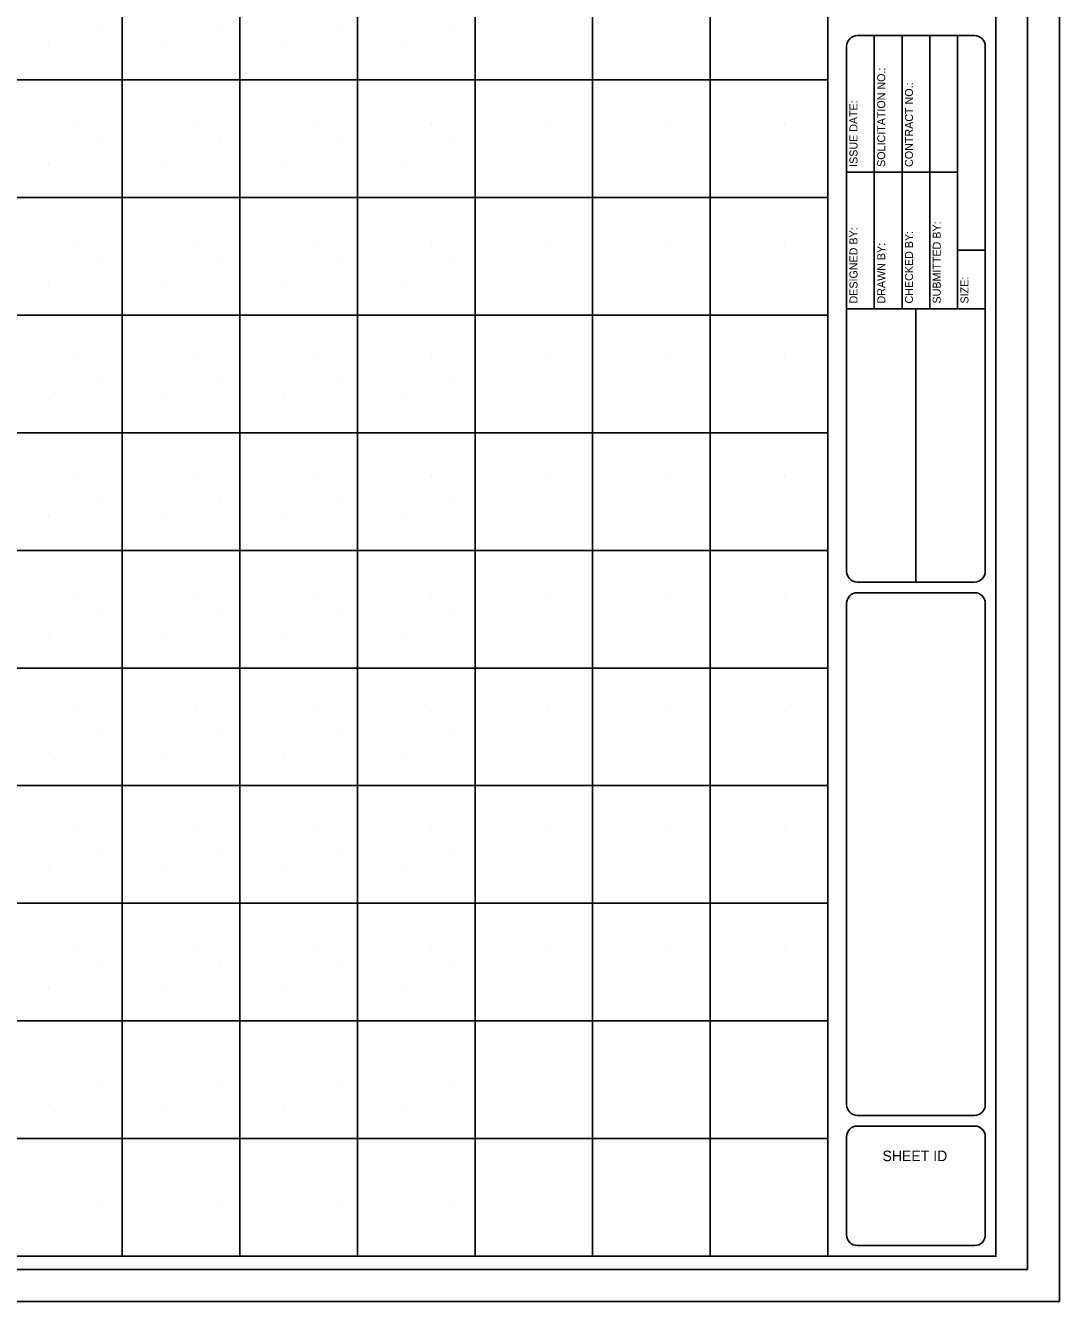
# Model space of a CAD drawing. Extents: x -0.05 to 1.19, y 0 to 0.86.
# Drawn here: x 0.8813 to 1.189, y 0 to 0.3796 of the extents above; entities that cross this region are included whole.
import ezdxf

# ---------------------------------------------------------------- set-up
doc = ezdxf.new("R2010")
doc.units = 0
for name, color, linetype in [('G-ANNO-NPLT', 7, 'Continuous'), ('G-ANNO-TEXT', 7, 'Continuous'), ('G-ANNO-TTLB', 7, 'Continuous'), ('G-ANNO-TTLB-GRID', 7, 'Continuous')]:
    doc.layers.add(name, color=color, linetype=linetype)

msp = doc.modelspace()

# ---------------------------------------------------------------- linework, layer by layer
at = {"layer": 'G-ANNO-NPLT'}
for p, q in [((0.904075, 0.3794687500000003), (0.904075, 0.3794687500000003)), ((0.939075, 0.3794687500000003), (0.939075, 0.3794687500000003)), ((0.9740749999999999, 0.3794687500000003), (0.9740749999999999, 0.3794687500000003)), ((1.009075, 0.3794687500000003), (1.009075, 0.3794687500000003)), ((0.888075, 0.3734687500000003), (0.888075, 0.3734687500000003)), ((0.923075, 0.3734687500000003), (0.923075, 0.3734687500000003)), ((0.958075, 0.3734687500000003), (0.958075, 0.3734687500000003)), ((0.9930749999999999, 0.3734687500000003), (0.9930749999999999, 0.3734687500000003)), ((0.897075, 0.35046874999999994), (0.897075, 0.35046874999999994)), ((0.932075, 0.35046874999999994), (0.932075, 0.35046874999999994)), ((0.9670749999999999, 0.35046874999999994), (0.9670749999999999, 0.35046874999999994)), ((1.002075, 0.35046874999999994), (1.002075, 0.35046874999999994)), ((1.037075, 0.35046874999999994), (1.037075, 0.35046874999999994)), ((1.072075, 0.35046874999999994), (1.072075, 0.35046874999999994)), ((1.107075, 0.35046874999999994), (1.107075, 0.35046874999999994)), ((0.904075, 0.34446875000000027), (0.904075, 0.34446875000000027)), ((0.939075, 0.34446875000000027), (0.939075, 0.34446875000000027)), ((0.9740749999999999, 0.34446875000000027), (0.9740749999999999, 0.34446875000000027)), ((1.009075, 0.34446875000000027), (1.009075, 0.34446875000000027)), ((0.888075, 0.33846875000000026), (0.888075, 0.33846875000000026)), ((0.923075, 0.33846875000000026), (0.923075, 0.33846875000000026)), ((0.958075, 0.33846875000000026), (0.958075, 0.33846875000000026)), ((0.9930749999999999, 0.33846875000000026), (0.9930749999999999, 0.33846875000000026)), ((0.897075, 0.3154687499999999), (0.897075, 0.3154687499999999)), ((0.932075, 0.3154687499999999), (0.932075, 0.3154687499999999)), ((0.9670749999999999, 0.3154687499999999), (0.9670749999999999, 0.3154687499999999)), ((1.002075, 0.3154687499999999), (1.002075, 0.3154687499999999)), ((1.037075, 0.3154687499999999), (1.037075, 0.3154687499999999)), ((1.072075, 0.3154687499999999), (1.072075, 0.3154687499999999)), ((1.107075, 0.3154687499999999), (1.107075, 0.3154687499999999)), ((0.904075, 0.3094687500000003), (0.904075, 0.3094687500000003)), ((0.939075, 0.3094687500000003), (0.939075, 0.3094687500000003)), ((0.9740749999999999, 0.3094687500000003), (0.9740749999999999, 0.3094687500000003)), ((1.009075, 0.3094687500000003), (1.009075, 0.3094687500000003)), ((0.888075, 0.3034687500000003), (0.888075, 0.3034687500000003)), ((0.923075, 0.3034687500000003), (0.923075, 0.3034687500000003)), ((0.958075, 0.3034687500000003), (0.958075, 0.3034687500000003)), ((0.9930749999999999, 0.3034687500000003), (0.9930749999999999, 0.3034687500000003)), ((0.897075, 0.28046874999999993), (0.897075, 0.28046874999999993)), ((0.932075, 0.28046874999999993), (0.932075, 0.28046874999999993)), ((0.9670749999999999, 0.28046874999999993), (0.9670749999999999, 0.28046874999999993)), ((1.002075, 0.28046874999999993), (1.002075, 0.28046874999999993)), ((1.037075, 0.28046874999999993), (1.037075, 0.28046874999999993)), ((1.072075, 0.28046874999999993), (1.072075, 0.28046874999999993)), ((1.107075, 0.28046874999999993), (1.107075, 0.28046874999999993)), ((0.904075, 0.27446875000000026), (0.904075, 0.27446875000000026)), ((0.939075, 0.27446875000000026), (0.939075, 0.27446875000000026)), ((0.9740749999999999, 0.27446875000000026), (0.9740749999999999, 0.27446875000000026)), ((1.009075, 0.27446875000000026), (1.009075, 0.27446875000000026)), ((0.888075, 0.26846875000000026), (0.888075, 0.26846875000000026)), ((0.923075, 0.26846875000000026), (0.923075, 0.26846875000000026)), ((0.958075, 0.26846875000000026), (0.958075, 0.26846875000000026)), ((0.9930749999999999, 0.26846875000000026), (0.9930749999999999, 0.26846875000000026)), ((0.897075, 0.24546874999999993), (0.897075, 0.24546874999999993)), ((0.932075, 0.24546874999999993), (0.932075, 0.24546874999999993)), ((0.9670749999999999, 0.24546874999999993), (0.9670749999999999, 0.24546874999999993)), ((1.002075, 0.24546874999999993), (1.002075, 0.24546874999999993)), ((1.037075, 0.24546874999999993), (1.037075, 0.24546874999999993)), ((1.072075, 0.24546874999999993), (1.072075, 0.24546874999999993)), ((1.107075, 0.24546874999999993), (1.107075, 0.24546874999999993)), ((0.904075, 0.23946875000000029), (0.904075, 0.23946875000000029)), ((0.939075, 0.23946875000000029), (0.939075, 0.23946875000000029)), ((0.9740749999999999, 0.23946875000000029), (0.9740749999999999, 0.23946875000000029)), ((1.009075, 0.23946875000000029), (1.009075, 0.23946875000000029)), ((0.888075, 0.23346875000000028), (0.888075, 0.23346875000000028)), ((0.923075, 0.23346875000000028), (0.923075, 0.23346875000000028)), ((0.958075, 0.23346875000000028), (0.958075, 0.23346875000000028)), ((0.9930749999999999, 0.23346875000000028), (0.9930749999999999, 0.23346875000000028)), ((0.897075, 0.21046874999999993), (0.897075, 0.21046874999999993)), ((0.932075, 0.21046874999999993), (0.932075, 0.21046874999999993)), ((0.9670749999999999, 0.21046874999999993), (0.9670749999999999, 0.21046874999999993)), ((1.002075, 0.21046874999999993), (1.002075, 0.21046874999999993)), ((1.037075, 0.21046874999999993), (1.037075, 0.21046874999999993)), ((1.072075, 0.21046874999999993), (1.072075, 0.21046874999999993)), ((1.107075, 0.21046874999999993), (1.107075, 0.21046874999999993)), ((0.904075, 0.20446875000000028), (0.904075, 0.20446875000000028)), ((0.939075, 0.20446875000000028), (0.939075, 0.20446875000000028)), ((0.9740749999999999, 0.20446875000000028), (0.9740749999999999, 0.20446875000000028)), ((1.009075, 0.20446875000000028), (1.009075, 0.20446875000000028)), ((0.888075, 0.19846875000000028), (0.888075, 0.19846875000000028)), ((0.923075, 0.19846875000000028), (0.923075, 0.19846875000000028)), ((0.958075, 0.19846875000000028), (0.958075, 0.19846875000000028)), ((0.9930749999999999, 0.19846875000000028), (0.9930749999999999, 0.19846875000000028)), ((0.897075, 0.17546874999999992), (0.897075, 0.17546874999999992)), ((0.932075, 0.17546874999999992), (0.932075, 0.17546874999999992)), ((0.9670749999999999, 0.17546874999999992), (0.9670749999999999, 0.17546874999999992)), ((1.002075, 0.17546874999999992), (1.002075, 0.17546874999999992)), ((1.037075, 0.17546874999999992), (1.037075, 0.17546874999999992)), ((1.072075, 0.17546874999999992), (1.072075, 0.17546874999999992)), ((1.107075, 0.17546874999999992), (1.107075, 0.17546874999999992)), ((0.904075, 0.16946875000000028), (0.904075, 0.16946875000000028)), ((0.939075, 0.16946875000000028), (0.939075, 0.16946875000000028)), ((0.9740749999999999, 0.16946875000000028), (0.9740749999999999, 0.16946875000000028)), ((1.009075, 0.16946875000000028), (1.009075, 0.16946875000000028)), ((0.888075, 0.16346875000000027), (0.888075, 0.16346875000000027)), ((0.923075, 0.16346875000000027), (0.923075, 0.16346875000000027)), ((0.958075, 0.16346875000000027), (0.958075, 0.16346875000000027)), ((0.9930749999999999, 0.16346875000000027), (0.9930749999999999, 0.16346875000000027)), ((0.897075, 0.14046874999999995), (0.897075, 0.14046874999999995)), ((0.932075, 0.14046874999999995), (0.932075, 0.14046874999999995)), ((0.9670749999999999, 0.14046874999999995), (0.9670749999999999, 0.14046874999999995)), ((1.002075, 0.14046874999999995), (1.002075, 0.14046874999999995)), ((1.037075, 0.14046874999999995), (1.037075, 0.14046874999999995)), ((1.072075, 0.14046874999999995), (1.072075, 0.14046874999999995)), ((1.107075, 0.14046874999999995), (1.107075, 0.14046874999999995)), ((0.904075, 0.13446875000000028), (0.904075, 0.13446875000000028)), ((0.939075, 0.13446875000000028), (0.939075, 0.13446875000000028)), ((0.9740749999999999, 0.13446875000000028), (0.9740749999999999, 0.13446875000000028)), ((1.009075, 0.13446875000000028), (1.009075, 0.13446875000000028)), ((0.888075, 0.1284687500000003), (0.888075, 0.1284687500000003)), ((0.923075, 0.1284687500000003), (0.923075, 0.1284687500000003)), ((0.958075, 0.1284687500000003), (0.958075, 0.1284687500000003)), ((0.9930749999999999, 0.1284687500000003), (0.9930749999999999, 0.1284687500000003)), ((0.897075, 0.10546874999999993), (0.897075, 0.10546874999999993)), ((0.932075, 0.10546874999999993), (0.932075, 0.10546874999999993)), ((0.9670749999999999, 0.10546874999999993), (0.9670749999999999, 0.10546874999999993)), ((1.002075, 0.10546874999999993), (1.002075, 0.10546874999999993)), ((1.037075, 0.10546874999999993), (1.037075, 0.10546874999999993)), ((1.072075, 0.10546874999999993), (1.072075, 0.10546874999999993)), ((1.107075, 0.10546874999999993), (1.107075, 0.10546874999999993)), ((0.904075, 0.09946875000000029), (0.904075, 0.09946875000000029)), ((0.939075, 0.09946875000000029), (0.939075, 0.09946875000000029)), ((0.9740749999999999, 0.09946875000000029), (0.9740749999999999, 0.09946875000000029)), ((1.009075, 0.09946875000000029), (1.009075, 0.09946875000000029)), ((0.888075, 0.09346875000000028), (0.888075, 0.09346875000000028)), ((0.923075, 0.09346875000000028), (0.923075, 0.09346875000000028)), ((0.958075, 0.09346875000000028), (0.958075, 0.09346875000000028)), ((0.9930749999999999, 0.09346875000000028), (0.9930749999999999, 0.09346875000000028)), ((0.904075, 0.06446875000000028), (0.904075, 0.06446875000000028)), ((0.939075, 0.06446875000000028), (0.939075, 0.06446875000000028)), ((0.9740749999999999, 0.06446875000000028), (0.9740749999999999, 0.06446875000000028)), ((1.009075, 0.06446875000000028), (1.009075, 0.06446875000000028)), ((0.888075, 0.05846875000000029), (0.888075, 0.05846875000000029)), ((0.923075, 0.05846875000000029), (0.923075, 0.05846875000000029)), ((0.958075, 0.05846875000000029), (0.958075, 0.05846875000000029)), ((0.9930749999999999, 0.05846875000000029), (0.9930749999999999, 0.05846875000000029)), ((0.904075, 0.02946875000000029), (0.904075, 0.02946875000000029)), ((0.939075, 0.02946875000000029), (0.939075, 0.02946875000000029)), ((0.9740749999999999, 0.02946875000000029), (0.9740749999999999, 0.02946875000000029)), ((1.009075, 0.02946875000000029), (1.009075, 0.02946875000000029))]:
    msp.add_line(p, q, dxfattribs=at)
msp.add_lwpolyline([(0.009524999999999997, 0.8314749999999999), (1.179475, 0.8314749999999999), (1.179475, 0.009525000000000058), (0.009524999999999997, 0.009524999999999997)], close=True, dxfattribs=at)
at = {"layer": 'G-ANNO-TTLB'}
for p, q in [((1.1338947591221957, 0.2953398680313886), (1.1338947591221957, 0.37661986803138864)), ((1.1421497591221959, 0.2953398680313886), (1.1421497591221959, 0.37661986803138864)), ((1.1504047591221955, 0.2953398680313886), (1.1504047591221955, 0.37661986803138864)), ((1.1586597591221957, 0.2953398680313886), (1.1586597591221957, 0.37661986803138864)), ((1.1586597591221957, 0.3359798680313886), (1.1256450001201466, 0.3359798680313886)), ((1.1669199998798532, 0.3127552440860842), (1.1586597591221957, 0.3127552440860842)), ((1.1256450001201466, 0.2953398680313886), (1.1669199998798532, 0.2953398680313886)), ((1.1462772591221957, 0.21405986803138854), (1.1462772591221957, 0.2953398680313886)), ((1.1462772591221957, 0.21405986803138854), (1.1462772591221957, 0.2953398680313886))]:
    msp.add_line(p, q, dxfattribs=at)
for points in [[(0, 0.841), (1.189, 0.841), (1.189, 0), (0, 0)], [(0.035074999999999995, 0.81846875), (1.1700949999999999, 0.81846875), (1.1700949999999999, 0.013468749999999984), (0.035074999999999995, 0.01346874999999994)], [(1.120075, 0.57346875), (1.1700949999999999, 0.57346875), (1.1700949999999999, 0.013468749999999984), (1.120075, 0.01346874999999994)]]:
    msp.add_lwpolyline(points, close=True, dxfattribs=at)
for points in [[(1.1637449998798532, 0.3766198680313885), (1.1288200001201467, 0.3766198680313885)], [(1.1256450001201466, 0.37344486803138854), (1.1256450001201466, 0.21723486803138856)], [(1.1669199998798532, 0.21723486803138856), (1.1669199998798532, 0.37344486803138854)], [(1.1288200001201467, 0.21405986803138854), (1.1637449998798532, 0.21405986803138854)], [(1.1637449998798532, 0.21088486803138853), (1.1288200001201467, 0.21088486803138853)], [(1.1256450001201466, 0.20770986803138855), (1.1256450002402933, 0.05855399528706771)], [(1.16692, 0.05855399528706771), (1.1669199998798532, 0.20770986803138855)], [(1.1288200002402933, 0.0553789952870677), (1.163745, 0.0553789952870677)], [(1.1288200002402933, 0.052203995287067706), (1.1637450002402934, 0.052203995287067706)], [(1.1256450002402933, 0.019817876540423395), (1.1256450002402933, 0.049028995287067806)], [(1.1669200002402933, 0.049028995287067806), (1.1669199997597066, 0.019819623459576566)], [(1.1637449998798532, 0.016643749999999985), (1.1288200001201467, 0.016643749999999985)]]:
    msp.add_lwpolyline(points, dxfattribs=at)
for centre, radius, start, end in [((1.1288200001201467, 0.37344486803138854), 0.003175, 90, 180), ((1.1637449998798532, 0.37344486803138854), 0.003175, 0, 90), ((1.1288200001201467, 0.21723486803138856), 0.003175, 180, 270), ((1.1637449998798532, 0.21723486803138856), 0.003175, 270, 0), ((1.1288200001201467, 0.20770986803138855), 0.003175, 90, 180), ((1.1637449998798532, 0.20770986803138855), 0.003175, 0, 90), ((1.1288200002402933, 0.05855399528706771), 0.003175, 180, 270), ((1.163745, 0.05855399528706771), 0.003175, 270, 0), ((1.1288200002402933, 0.049028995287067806), 0.003174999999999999, 90, 180), ((1.1637450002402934, 0.049028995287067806), 0.003174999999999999, 0, 90), ((1.1288200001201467, 0.019818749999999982), 0.0031749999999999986, 180.01576237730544, 270), ((1.1637449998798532, 0.019818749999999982), 0.003174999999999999, 270, 0.015762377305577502)]:
    msp.add_arc(centre, radius, start, end, dxfattribs=at)
at = {"layer": 'G-ANNO-TTLB-GRID'}
for p, q in [((0.910075, 0.81846875), (0.910075, 0.013468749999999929)), ((0.945075, 0.81846875), (0.945075, 0.013468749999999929)), ((0.9800749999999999, 0.81846875), (0.9800749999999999, 0.013468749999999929)), ((1.015075, 0.81846875), (1.015075, 0.013468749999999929)), ((1.0500749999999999, 0.81846875), (1.0500749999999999, 0.013468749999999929)), ((1.085075, 0.81846875), (1.085075, 0.013468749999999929)), ((0.035074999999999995, 0.36346874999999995), (1.120075, 0.36346874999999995)), ((0.035074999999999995, 0.3284687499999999), (1.120075, 0.3284687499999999)), ((0.035074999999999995, 0.29346874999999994), (1.120075, 0.29346874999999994)), ((0.035074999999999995, 0.2584687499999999), (1.120075, 0.2584687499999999)), ((0.035074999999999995, 0.22346874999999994), (1.120075, 0.22346874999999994)), ((0.035074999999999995, 0.18846874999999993), (1.120075, 0.18846874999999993)), ((0.035074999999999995, 0.15346874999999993), (1.120075, 0.15346874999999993)), ((0.035074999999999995, 0.11846874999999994), (1.120075, 0.11846874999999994)), ((0.035074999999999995, 0.08346874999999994), (1.120075, 0.08346874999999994)), ((0.035074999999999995, 0.04846874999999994), (1.120075, 0.04846874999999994))]:
    msp.add_line(p, q, dxfattribs=at)

# ---------------------------------------------------------------- texts
at = {"layer": 'G-ANNO-TEXT'}
for s, p in [('SOLICITATION NO.:', (1.1371491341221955, 0.3375673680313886)), ('CONTRACT NO.:', (1.145404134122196, 0.3375673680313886)), ('ISSUE DATE:', (1.1288941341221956, 0.3375673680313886)), ('DESIGNED BY:', (1.1288941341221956, 0.2969273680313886)), ('SUBMITTED BY:', (1.1536591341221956, 0.2969273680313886)), ('CHECKED BY:', (1.1454041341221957, 0.2969273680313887)), ('DRAWN BY:', (1.1371491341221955, 0.2969273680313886)), ('SIZE:', (1.1619141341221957, 0.2969273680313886))]:
    msp.add_text(s, height=0.0023812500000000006, rotation=89.99999999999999, dxfattribs=at).set_placement(p)
msp.add_text('SHEET ID', height=0.0031251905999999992, dxfattribs=at).set_placement((1.1363292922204, 0.04175161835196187))

doc.saveas('drawing.dxf')
